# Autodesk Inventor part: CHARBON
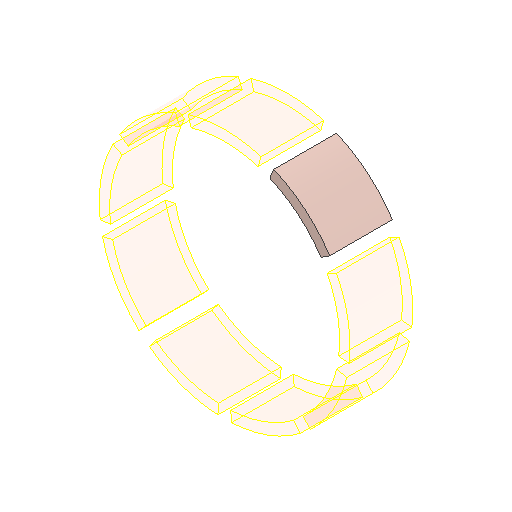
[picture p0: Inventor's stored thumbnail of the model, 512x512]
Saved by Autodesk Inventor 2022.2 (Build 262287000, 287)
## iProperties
Created: 2025-01
Part Number: CHARBON
Material: Generico
Document SubType Name: Modeling
Designer: 18907419
Density: 1 g/cm^3
Appearance: Default
Author: 18907419
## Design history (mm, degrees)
feature "CHARBON"
feature "Composto1"
node "Solido1"
node "Superf1"
